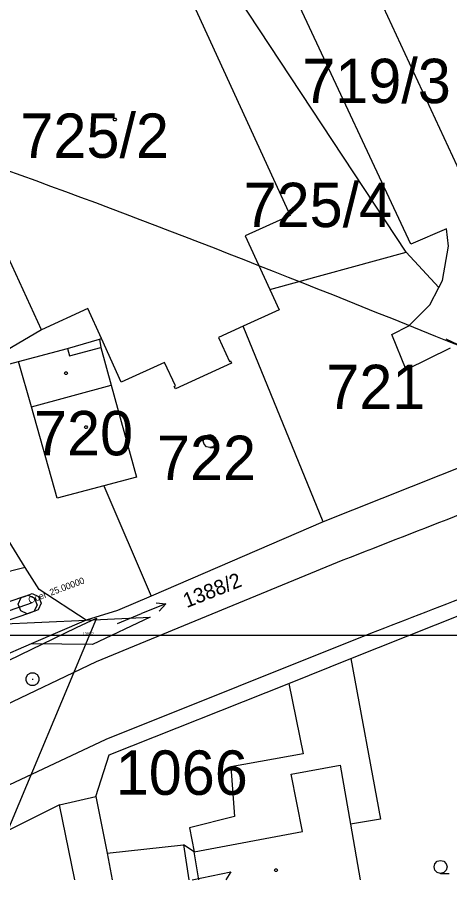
# Model space of a CAD drawing. Extents: x -510185 to -506993, y -1126306 to -1123642.
# Drawn here: x -508127.6 to -508077.9, y -1126306.3 to -1126207.2 of the extents above; entities that cross this region are included whole.
import ezdxf

# ---------------------------------------------------------------- set-up
doc = ezdxf.new("R2010")
doc.units = 0
for name, color, linetype in [('ochranná pásma', 7, 'Continuous'), ('parcelni hranice', 7, 'Continuous'), ('u_plyn ochranné pásmo', 7, 'Continuous'), ('u_plyn popis', 7, 'Continuous'), ('u_plyn STL', 7, 'Continuous'), ('u_ČEZ nadzemní nn', 7, 'Continuous'), ('x_formát_rám', 7, 'Continuous'), ('ˇ2', 7, 'Continuous'), ('ˇ3', 7, 'Continuous'), ('ˇ4', 7, 'Continuous'), ('ˇ5', 7, 'Continuous'), ('ˇ7', 7, 'Continuous'), ('ˇ8', 7, 'Continuous')]:
    doc.layers.add(name, color=color, linetype=linetype)

msp = doc.modelspace()

# ---------------------------------------------------------------- linework, layer by layer
at = {"layer": 'ochranná pásma'}
msp.add_line((-508078.379, -1126244.157), (-508017.309, -1126273.077), dxfattribs=at)
msp.add_spline([(-508301.355, -1126182.251), (-508249.273, -1126191.292), (-508186.119, -1126206.671), (-508130.632, -1126224.108), (-508076.147, -1126245.192)], degree=3, dxfattribs=at)
at = {"layer": 'parcelni hranice'}
for p, q in [((-508082.91, -1126234.17), (-508105.49, -1126199.91)), ((-508109.33, -1126201.38), (-508096.26, -1126229.96)), ((-508087.27, -1126202.3), (-508074.25, -1126230.42)), ((-508082.39, -1126233.27), (-508095.12, -1126206)), ((-508124.81, -1126243.11), (-508137.71, -1126215.05)), ((-508096.26, -1126229.96), (-508101.4, -1126232.32)), ((-508101.4, -1126232.32), (-508098.58, -1126238.47)), ((-508078.3, -1126231.48), (-508082.39, -1126233.27)), ((-508078.05, -1126233.49), (-508078.3, -1126231.48)), ((-508098.58, -1126238.47), (-508082.91, -1126234.17)), ((-508082.91, -1126234.17), (-508079.16, -1126238.25)), ((-508078.75, -1126237.45), (-508078.05, -1126233.49)), ((-508080.19, -1126240.24), (-508079.16, -1126238.25)), ((-508079.16, -1126238.25), (-508078.75, -1126237.45)), ((-508098.58, -1126238.47), (-508097.52, -1126240.79)), ((-508082.62, -1126242.63), (-508080.19, -1126240.24)), ((-508119.51, -1126240.66), (-508124.81, -1126243.11)), ((-508117.94, -1126244.12), (-508119.51, -1126240.66)), ((-508097.52, -1126240.79), (-508101.63, -1126242.68)), ((-508124.81, -1126243.11), (-508129.58, -1126245.9)), ((-508101.63, -1126242.68), (-508104.49, -1126243.99)), ((-508092.45, -1126265.18), (-508101.63, -1126242.68)), ((-508084.56, -1126243.64), (-508082.62, -1126242.63)), ((-508121.82, -1126245.27), (-508118.14, -1126244.18)), ((-508118.14, -1126244.18), (-508117.94, -1126244.12)), ((-508118.14, -1126244.18), (-508118.01, -1126245.14)), ((-508115.68, -1126249.12), (-508117.94, -1126244.12)), ((-508104.49, -1126243.99), (-508103.23, -1126246.74)), ((-508082.93, -1126247.69), (-508084.56, -1126243.64)), ((-508127.45, -1126246.74), (-508121.82, -1126245.27)), ((-508118.01, -1126245.14), (-508116.82, -1126249.46)), ((-508077.86, -1126245.21), (-508082.93, -1126247.69)), ((-508139.41, -1126249.9), (-508127.45, -1126246.74)), ((-508110.69, -1126246.88), (-508115.68, -1126249.12)), ((-508109.43, -1126249.55), (-508110.69, -1126246.88)), ((-508102.97, -1126246.95), (-508109.43, -1126249.89)), ((-508103.23, -1126246.74), (-508103.1, -1126246.68)), ((-508103.1, -1126246.68), (-508102.97, -1126246.95)), ((-508126.68, -1126270.41), (-508139.41, -1126249.9)), ((-508116.82, -1126249.46), (-508113.89, -1126260.04)), ((-508109.56, -1126249.62), (-508109.43, -1126249.55)), ((-508109.43, -1126249.89), (-508109.56, -1126249.62)), ((-508064.62, -1126254.08), (-508092.45, -1126265.18)), ((-508113.89, -1126260.04), (-508117.65, -1126261.05)), ((-508117.65, -1126261.05), (-508112.21, -1126273.72)), ((-508092.45, -1126265.18), (-508112.21, -1126273.72)), ((-508126.68, -1126270.41), (-508147.62, -1126275.69)), ((-508125.1, -1126272.94), (-508126.68, -1126270.41)), ((-508119.67, -1126276.48), (-508125.1, -1126272.94)), ((-508112.21, -1126273.72), (-508116.07, -1126275.38)), ((-508116.07, -1126275.38), (-508119.67, -1126276.48)), ((-508089.27, -1126280.89), (-508076.36, -1126275.74)), ((-508166.34, -1126278.63), (-508119.67, -1126276.48)), ((-508119.67, -1126276.48), (-508126, -1126279.2)), ((-508119.67, -1126276.48), (-508112.35, -1126276.14)), ((-508112.35, -1126276.14), (-508118.96, -1126279.28)), ((-508126, -1126279.2), (-508140.36, -1126285.37)), ((-508118.96, -1126279.28), (-508126, -1126279.2)), ((-508096.42, -1126283.74), (-508089.27, -1126280.89)), ((-508089.27, -1126280.89), (-508085.87, -1126299.34)), ((-508117.03, -1126291.97), (-508096.42, -1126283.74)), ((-508096.42, -1126283.74), (-508094.74, -1126291.85)), ((-508094.74, -1126291.85), (-508103.07, -1126293.35)), ((-508118.56, -1126296.73), (-508117.03, -1126291.97)), ((-508103.07, -1126293.35), (-508102.63, -1126299.06)), ((-508122.74, -1126297.69), (-508118.56, -1126296.73)), ((-508118.56, -1126296.73), (-508117.29, -1126303.26)), ((-508122.74, -1126297.69), (-508138.68, -1126305.62)), ((-508120.983, -1126306.312), (-508122.74, -1126297.69)), ((-508102.63, -1126299.06), (-508107.83, -1126300.36)), ((-508085.87, -1126299.34), (-508089.32, -1126299.94)), ((-508107.83, -1126300.36), (-508107.29, -1126303.12)), ((-508089.32, -1126299.94), (-508088.214, -1126306.312)), ((-508117.29, -1126303.26), (-508108.52, -1126302.29)), ((-508108.52, -1126302.29), (-508107.88, -1126306.312)), ((-508107.29, -1126303.12), (-508108.52, -1126302.29)), ((-508117.29, -1126303.26), (-508116.695, -1126306.312)), ((-508106.732, -1126306.312), (-508107.29, -1126303.12))]:
    msp.add_line(p, q, dxfattribs=at)
at = {"layer": 'u_plyn ochranné pásmo'}
msp.add_lwpolyline([(-508131.938, -1126275.489), (-508126.728, -1126273.727), (-508126.336, -1126273.594), (-508125.594, -1126273.961), (-508125.461, -1126274.354), (-508125.328, -1126274.746), (-508125.695, -1126275.488), (-508126.088, -1126275.621), (-508131.298, -1126277.383)], dxfattribs=at)
msp.add_lwpolyline([(-508124.858, -1126274.54), (-508125.203, -1126275.293), (-508125.592, -1126275.437), (-508126.06, -1126275.611), (-508126.448, -1126275.756), (-508127.201, -1126275.411), (-508127.345, -1126275.022), (-508127.49, -1126274.634), (-508127.145, -1126273.881), (-508126.756, -1126273.737), (-508126.288, -1126273.563), (-508125.9, -1126273.418), (-508125.147, -1126273.763), (-508125.003, -1126274.152)], close=True, dxfattribs=at)
at = {"layer": 'u_plyn STL'}
for p, q in [((-508126.408, -1126274.674), (-508131.618, -1126276.436)), ((-508125.94, -1126274.5), (-508126.408, -1126274.674))]:
    msp.add_line(p, q, dxfattribs=at)
at = {"layer": 'u_ČEZ nadzemní nn'}
for p, q in [((-508118.488, -1126276.234), (-508131.089, -1126306.312)), ((-508120.788, -1126277.338), (-508118.488, -1126276.234)), ((-508154.273, -1126293.407), (-508120.788, -1126277.338))]:
    msp.add_line(p, q, dxfattribs=at)
msp.add_lwpolyline([(-508107.514, -1126306.312), (-508103.08, -1126305.41), (-508103.62, -1126306.312)], dxfattribs=at)
at = {"layer": 'x_formát_rám'}
msp.add_lwpolyline([(-510158.515, -1126278.21), (-507008.515, -1126278.21), (-507008.515, -1123673.61), (-510158.515, -1123673.61)], close=True, dxfattribs=at)
at = {"layer": 'ˇ3'}
for points in [[(-508105.49, -1126256.64), (-508105.865, -1126256.539), (-508106.139, -1126256.265), (-508106.24, -1126255.89), (-508106.139, -1126255.515), (-508105.865, -1126255.241), (-508105.49, -1126255.14), (-508105.115, -1126255.241), (-508104.841, -1126255.515), (-508104.74, -1126255.89), (-508104.841, -1126256.265), (-508105.115, -1126256.539), (-508105.49, -1126256.64), (-508104.49, -1126256.641)], [(-508078.97, -1126305.59), (-508079.345, -1126305.489), (-508079.619, -1126305.215), (-508079.72, -1126304.84), (-508079.619, -1126304.465), (-508079.345, -1126304.191), (-508078.97, -1126304.09), (-508078.595, -1126304.191), (-508078.321, -1126304.465), (-508078.22, -1126304.84), (-508078.321, -1126305.215), (-508078.595, -1126305.489), (-508078.97, -1126305.59), (-508077.97, -1126305.591)]]:
    msp.add_lwpolyline(points, dxfattribs=at)
at = {"layer": 'ˇ4'}
for p, q in [((-508121.82, -1126245.27), (-508121.6, -1126246.1)), ((-508121.6, -1126246.1), (-508118.01, -1126245.14)), ((-508125.98, -1126251.97), (-508127.45, -1126246.74)), ((-508125.98, -1126251.97), (-508116.82, -1126249.46)), ((-508123.02, -1126262.45), (-508125.98, -1126251.97)), ((-508117.65, -1126261.05), (-508123.02, -1126262.45)), ((-508118.5, -1126281.21), (-508090.15, -1126269.56)), ((-508087, -1126278.02), (-508117.44, -1126290.19)), ((-508144.48, -1126293.64), (-508118.5, -1126281.21)), ((-508117.44, -1126290.19), (-508140.82, -1126301.22)), ((-508096.13, -1126294.18), (-508090.5, -1126293.15)), ((-508090.5, -1126293.15), (-508089.32, -1126299.94)), ((-508094.84, -1126300.77), (-508096.13, -1126294.18)), ((-508107.29, -1126303.12), (-508094.84, -1126300.77))]:
    msp.add_line(p, q, dxfattribs=at)
for points in [[(-508090.15, -1126269.56), (-508062.8, -1126259.08), (-508026.16, -1126246.73)], [(-508040.8, -1126260.86), (-508061.66, -1126268.33), (-508087, -1126278.02)]]:
    msp.add_spline(points, degree=3, dxfattribs=at)
at = {"layer": 'ˇ5'}
for points in [[(-508116.303, -1126218.768), (-508116.215, -1126218.92), (-508116.303, -1126219.072), (-508116.477, -1126219.072), (-508116.565, -1126218.92), (-508116.477, -1126218.768)], [(-508121.913, -1126247.938), (-508121.825, -1126248.09), (-508121.913, -1126248.242), (-508122.087, -1126248.242), (-508122.175, -1126248.09), (-508122.087, -1126247.938)], [(-508119.633, -1126254.128), (-508119.545, -1126254.28), (-508119.633, -1126254.432), (-508119.807, -1126254.432), (-508119.895, -1126254.28), (-508119.807, -1126254.128)], [(-508097.793, -1126305.068), (-508097.705, -1126305.22), (-508097.793, -1126305.372), (-508097.967, -1126305.372), (-508098.055, -1126305.22), (-508097.967, -1126305.068)]]:
    msp.add_lwpolyline(points, close=True, dxfattribs=at)
at = {"layer": 'ˇ7'}
msp.add_line((-508116.1, -1126276.86), (-508113.32, -1126275.72), dxfattribs=at)
for points in [[(-508110.545, -1126274.581), (-508113.32, -1126275.72)], [(-508111.66, -1126274.498), (-508110.545, -1126274.581), (-508111.28, -1126275.423)]]:
    msp.add_lwpolyline(points, dxfattribs=at)
at = {"layer": 'ˇ8'}
msp.add_lwpolyline([(-508125.646, -1126282.526), (-508125.31, -1126282.72), (-508125.116, -1126283.056), (-508125.116, -1126283.444), (-508125.31, -1126283.78), (-508125.646, -1126283.974), (-508126.034, -1126283.974), (-508126.37, -1126283.78), (-508126.564, -1126283.444), (-508126.564, -1126283.056), (-508126.37, -1126282.72), (-508126.034, -1126282.526)], close=True, dxfattribs=at)
msp.add_lwpolyline([(-508125.89, -1126283.25), (-508125.79, -1126283.25)], dxfattribs=at)

# ---------------------------------------------------------------- texts
at = {"layer": 'u_plyn popis'}
msp.add_text('Ocel  25.00000', height=0.75, rotation=20.39501, dxfattribs=at).set_placement((-508126.174, -1126274.587))
at = {"layer": 'ˇ2'}
for s, height, p in [('719/3', 5.1, (-508094.856, -1126217.05)), ('725/2', 5.1, (-508127.241, -1126223.34)), ('725/4', 5.1, (-508101.601, -1126231.3)), ('721', 5.1, (-508092.099, -1126252.22)), ('720', 5.1, (-508125.673, -1126257.53)), ('722', 5.1, (-508111.544, -1126260.37)), ('1388/2', 0.3, (-508120.064, -1126278.19)), ('1066', 5.1, (-508116.286, -1126296.55))]:
    msp.add_text(s, height=height, dxfattribs=at).set_placement(p)
at = {"layer": 'ˇ7'}
msp.add_text('1388/2', height=1.7, rotation=21.60051, dxfattribs=at).set_placement((-508108.132, -1126275.096))

doc.saveas('drawing.dxf')
